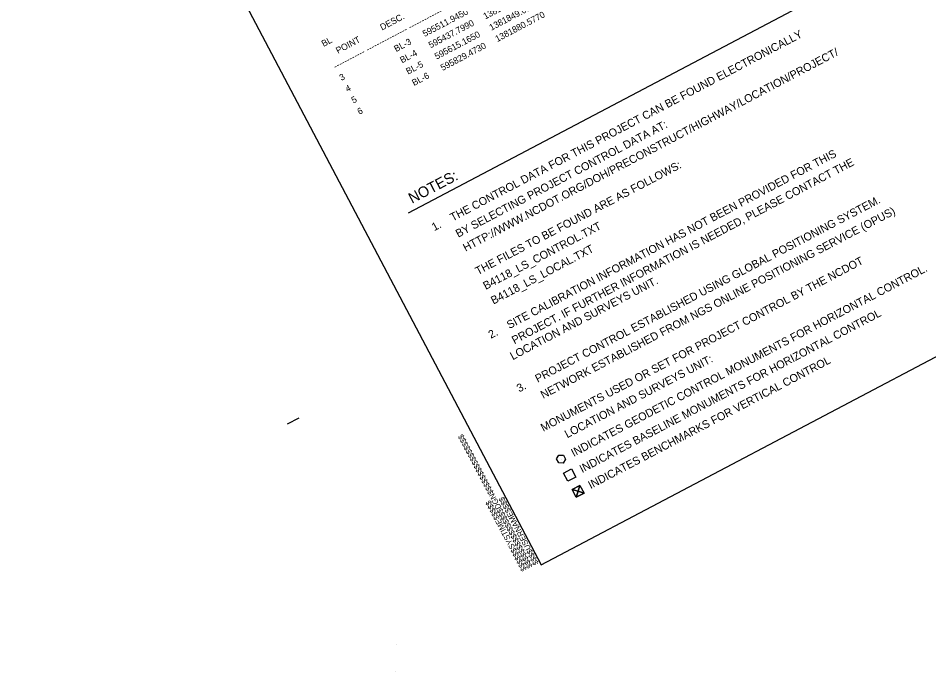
# Model space of a CAD drawing. Extents: x 1379448 to 1382868, y 593769 to 596827.
# Drawn here: x 1379496 to 1380979, y 593769 to 594833 of the extents above; entities that cross this region are included whole.
import ezdxf

# ---------------------------------------------------------------- set-up
doc = ezdxf.new("R2010")
doc.units = 0
for name, color, linetype in [('CTL Bench Mark CELL', 7, 'Continuous'), ('CTL GPS Vertical CELL', 7, 'Continuous'), ('CTL Sheet Border CELL', 7, 'Continuous'), ('CTL Sheet Notes CELL', 7, 'Continuous'), ('CTL Sheet Text', 7, 'Continuous'), ('CTL Supplemental Horizontal and Vertical CELL', 7, 'Continuous')]:
    doc.layers.add(name, color=color, linetype=linetype)

# ---------------------------------------------------------------- blocks, each defined once
blk = doc.blocks.new('CTL BENCH MARK')
at = {"layer": 'CTL Bench Mark CELL'}
blk.add_line((0, 0), (0, 0), dxfattribs=at)
blk.add_lwpolyline([(-0.072, 0.07175), (0.07175, 0.07175), (0.07175, -0.072), (-0.072, -0.072)], close=True, dxfattribs=at)
for points in [[(0.07175, 0.07175), (-0.072, -0.072), (-0.000125, -0.000125), (0.07175, -0.072), (-0.072, 0.07175)], [(-0.000125, -0.000125), (0.07175, 0.07175), (-0.072, 0.07175), (-0.000125, -0.000125)], [(-0.000125, -0.000125), (-0.072, -0.072), (0.07175, -0.072), (-0.000125, -0.000125)]]:
    blk.add_lwpolyline(points, dxfattribs=at)
blk = doc.blocks.new('CTL SUPPLEMENTAL HORIZONTAL AND VERTICAL')
at = {"layer": 'CTL Supplemental Horizontal and Vertical CELL'}
blk.add_line((0, 0), (0, 0), dxfattribs=at)
blk.add_lwpolyline([(-0.0735, 0.074), (0.07475, 0.074), (0.07475, -0.0745), (-0.0735, -0.0745)], close=True, dxfattribs=at)
blk = doc.blocks.new('CTL GPS VERTICAL')
at = {"layer": 'CTL GPS Vertical CELL'}
blk.add_line((-0.001, 0), (-0.001, 0), dxfattribs=at)
blk.add_lwpolyline([(-0.065, 0.037), (0, 0.074), (0.065, 0.038), (0.064, -0.036), (-0.001, -0.074), (-0.065, -0.038)], close=True, dxfattribs=at)

msp = doc.modelspace()

# ---------------------------------------------------------------- linework, layer by layer
at = {"layer": 'CTL Sheet Border CELL'}
for p, q in [((1379934.8, 594172.1), (1379954, 594182.2)), ((1380347.7, 593942.5), (1380347.7, 593942.5)), ((1380347.7, 593942.5), (1380347.7, 593942.5)), ((1380347.7, 593942.5), (1380347.7, 593942.5)), ((1380347.7, 593942.5), (1380347.7, 593942.5)), ((1380347.7, 593942.5), (1380347.7, 593942.5)), ((1380347.7, 593942.5), (1380347.7, 593942.5)), ((1380347.7, 593942.5), (1380347.7, 593942.5)), ((1380347.7, 593942.5), (1380347.7, 593942.5)), ((1380347.7, 593942.5), (1380347.7, 593942.5)), ((1380347.7, 593942.5), (1380347.7, 593942.5)), ((1380347.7, 593942.5), (1380347.7, 593942.5)), ((1380112.9, 593813.7), (1380112.9, 593813.7)), ((1380111.1, 593768.6), (1380111.1, 593768.6))]:
    msp.add_line(p, q, dxfattribs=at)
msp.add_lwpolyline([(1381803.8, 596774.4), (1379496.1, 595557.9), (1380347.7, 593942.5), (1382655.4, 595159.1)], close=True, dxfattribs=at)
msp.add_lwpolyline([(1380405.4, 593972.9), (1380405.4, 593972.9)], dxfattribs=at)
msp.add_lwpolyline([(1380405.4, 593972.9), (1380405.4, 593972.9)], dxfattribs=at)
at = {"layer": 'CTL Sheet Notes CELL'}
msp.add_line((1380131.8, 594515.8), (1380844.1, 594891.3), dxfattribs=at)

# ---------------------------------------------------------------- block references
at = {"layer": 'CTL Bench Mark CELL', "xscale": 99.99999999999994, "yscale": 99.99999999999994, "rotation": 27.804232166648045}
msp.add_blockref('CTL BENCH MARK', (1380408.1, 594062.5), dxfattribs=at)
at = {"layer": 'CTL GPS Vertical CELL', "xscale": 99.99999999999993, "yscale": 99.9999999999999, "rotation": 27.98631238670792}
msp.add_blockref('CTL GPS VERTICAL', (1380380.4, 594115), dxfattribs=at)
at = {"layer": 'CTL Supplemental Horizontal and Vertical CELL', "xscale": 99.99999999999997, "yscale": 99.99999999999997, "rotation": 27.785895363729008}
msp.add_blockref('CTL SUPPLEMENTAL HORIZONTAL AND VERTICAL', (1380394.2, 594088.8), dxfattribs=at)

# ---------------------------------------------------------------- texts
at = {"layer": 'CTL Sheet Border CELL'}
for s, p in [('$$$$$$$$$$$$$$$$DGN$$$$$$$$$$$$$$$$', (1380334.1, 593940)), ('$$$$$$SYSTIME$$$$$', (1380324.7, 593935.1)), ('$$$$USERNAME$$$$', (1380344.2, 593945.3))]:
    msp.add_text(s, height=9.13, rotation=117.7977, dxfattribs=at).set_placement(p)
at = {"layer": 'CTL Sheet Notes CELL'}
for s, height, rotation, p in [('1.    THE CONTROL DATA FOR THIS PROJECT CAN BE FOUND ELECTRONICALLY', 13.044, 27.7977, (1380173.8, 594485.9)), ('HTTP://WWW.NCDOT.ORG/DOH/PRECONSTRUCT/HIGHWAY/LOCATION/PROJECT/', 13.044, 27.7977, (1380224.8, 594452.4)), ('BY SELECTING PROJECT CONTROL DATA AT:', 13.044, 27.7977, (1380212.8, 594475.3)), ('2.    SITE CALIBRATION INFORMATION HAS NOT BEEN PROVIDED FOR THIS', 13.044, 27.7977, (1380266.1, 594310.7)), ('PROJECT. IF FURTHER INFORMATION IS NEEDED, PLEASE CONTACT THE ', 13.044, 27.7977, (1380304.3, 594301.8)), ('THE FILES TO BE FOUND ARE AS FOLLOWS:', 13.044, 27.7977, (1380244.9, 594414.3)), ('NOTES:', 17.39, 27.6925, (1380137.5, 594530.5)), ('3.    PROJECT CONTROL ESTABLISHED USING GLOBAL POSITIONING SYSTEM.', 13.044, 27.6925, (1380312.2, 594223.4)), ('NETWORK ESTABLISHED FROM NGS ONLINE POSITIONING SERVICE (OPUS)', 13.044, 27.6925, (1380351.2, 594212.8)), ('B4118_LS_CONTROL.TXT', 13.044, 27.7977, (1380257.6, 594390.3)), ('B4118_LS_LOCAL.TXT', 13.044, 27.7977, (1380270.2, 594366.4)), ('MONUMENTS USED OR SET FOR PROJECT CONTROL BY THE NCDOT', 13.044, 27.6925, (1380351.4, 594159.3)), ('INDICATES GEODETIC CONTROL MONUMENTS FOR HORIZONTAL CONTROL.', 13.044, 27.6925, (1380400.9, 594118.4)), ('LOCATION AND SURVEYS UNIT.', 13.044, 27.7977, (1380301.6, 594275.8)), ('INDICATES BASELINE MONUMENTS FOR HORIZONTAL CONTROL ', 13.044, 27.6925, (1380414.7, 594092.2)), ('LOCATION AND SURVEYS UNIT:', 13.044, 27.6925, (1380390.4, 594148.7)), ('INDICATES BENCHMARKS FOR VERTICAL CONTROL ', 13.044, 27.6925, (1380428.6, 594066))]:
    msp.add_text(s, height=height, rotation=rotation, dxfattribs=at).set_placement(p)
at = {"layer": 'CTL Sheet Text'}
for s, height, p in [('    POINT          DESC.           NORTH             EAST          ELEVATION           L STATION       OFFSET', 10.4167, (1380003.2, 594767.5)), ('3                        BL-3      595511.9450     1381263.0910           673.40      OUTSIDE PROJECT LIMITS                 ', 10.4167, (1380022.6, 594730.6)), ('4                        BL-4      595437.7990     1381525.5930           667.25         10+68.66         17.88 RT', 10.4167, (1380032.3, 594712.2)), ('------------ ---------------- ---------------- ---------------- ---------------- ---------------- ----------------', 10.4167, (1380012.9, 594749.1)), ('5                        BL-5      595615.1650     1381849.6980           663.12         14+30.97         13.34 RT', 10.4167, (1380042.1, 594693.8)), ('6                        BL-6      595829.4730     1381880.5770           670.58      OUTSIDE PROJECT LIMITS                 ', 10.4167, (1380051.8, 594675.3)), ('BL', 10.42, (1379993.5, 594785.9))]:
    msp.add_text(s, height=height, rotation=27.7977, dxfattribs=at).set_placement(p)

doc.saveas('drawing.dxf')
